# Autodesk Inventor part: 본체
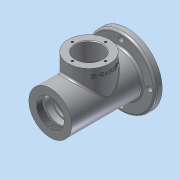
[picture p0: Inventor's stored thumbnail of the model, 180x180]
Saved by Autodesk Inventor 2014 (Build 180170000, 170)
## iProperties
Created: 2016-08
Part Number: 본체
Material: 알루미늄 6061
Document SubType Name: Modeling
Designer: 406-0014
Density: 2.71 g/cm^3
Appearance: 알루미늄 - 평지
Mass: 731.657 g
Surface Area: 616.228 cm^2
Volume: 269.984 cm^3
Author: 406-0014
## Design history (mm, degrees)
sketch "스케치1"
  geometry: C1 r 50 at (0, 0); 1 further point
  constraints: 1 centre point, 1 coincident
  dimensions: "d0" = 100 diameter of C1
extrude "돌출1" new body sketch "스케치1" distance "d1" = 10; taper "d2" = 0 deg
sketch "스케치2"
  geometry: C1 r 50 at (0, 0) reference; C2 r 31 at (0, 0)
  constraints: 1 centre point, 1 coincident
  dimensions: "d3" = 62 diameter of C2
extrude "돌출2" join sketch "스케치2" distance "d4" = 3; taper "d5" = 0 deg
sketch "스케치3"
  geometry: C1 r 50 at (0, 0) reference; C2 r 31 at (0, 0)
  constraints: 1 centre point, 1 coincident
  dimensions: "d6" = 62 diameter of C2
extrude "돌출3" join sketch "스케치3" distance "d7" = 102; taper "d8" = 0 deg
node "작업 평면1"
sketch "스케치4"
  geometry: L1 (-31, -102)-(31, -102) reference; C1 r 30 at (0, -46); 1 further point
  constraints: 1 centre point, 1 vertical alignment
  dimensions: "d10" = 60 diameter of C1; "d11" = 56 distance from line of L1 C1.centre
extrude "돌출4" join sketch "스케치4" stored distance "d12" = 102; taper "d13" = 0 deg
sketch "스케치5"
  geometry: C1 r 31 at (0, 0) reference; C2 r 50 at (0, 0) reference; 1 further point
  constraints: 1 coincident
hole "구멍1" sketch "스케치5" at (0, 0) diameter "d14" = 40.376; stored, may be unused: countersink angle "d18" = 90 deg, drill point angle "d20" = 0 deg; dims "d15" = 9, "d16" = 4, "d17" = 2, "d19" = 9
sketch "스케치6"
  geometry: L1 (0, -102.598)-(0, 13); L2 (-20.188, -93)-(20.188, -93) reference; L3 (0, -93)-(-24, -93); L4 (-24, -93)-(-24, -90); L5 (-24, -90)-(-20, -90); L6 (-20, -90)-(-20, -81); L7 (-20, -81)-(-17.5, -81); L8 (-17.5, -81)-(-17.5, -77.75); L9 (-17.5, -77.75)-(-18.5, -77.75); L10 (-18.5, -77.75)-(-18.5, -76); L11 (-18.5, -76)-(-17.5, -76); L12 (-17.5, -76)-(-17.5, -65); L13 (-17.5, -65)-(-26, -65); L14 (-26, -65)-(-26, -27); L15 (-26, -27)-(0, -27); L16 (20.188, -102)-(-20.188, -102) reference; L17 (-49, -16)-(-49, -76) reference; L18 (0, -93)-(0, -27); 3 further points
  constraints: 30 end point, 7 parallel, 7 perpendicular, 3 midpoint, 1 collinear, 1 horizontal alignment, 1 point on line, 1 vertical, 1 vertical alignment
  dimensions: "d23" = 3 distance between parallel lines of L5 L3; "d24" = 21 distance between parallel lines of L7 L16; "d25" = 1.75 distance between parallel lines of L9 L11; "d26" = 37 diameter of L10 L1; "d27" = 48 diameter of L4 L1; "d28" = 40 diameter of L6 L1; "d29" = 35 diameter of L8 L1; "d30" = 26 distance between parallel lines of L11 L16; "d31" = 35 diameter of L12 L1; "d32" = 52 diameter of L14 L1; "d45" = 38 distance between parallel lines of L15 L13; "d46" = 115.59757 distance of L1.start L1.end
revolve "회전1" sketch "스케치6" stored, may be unused: angle "d47" = 90 deg
sketch "스케치7"
  geometry: L1 (0, 15.236)-(0, -119.929); L2 (-26, -27)-(26, -27) reference; L3 (31, 13)-(-31, 13) reference; L4 (-17.5, -27)-(-17.5, -16.7); L5 (-17.5, -16.7)-(-16.5, -16.7); L6 (-16.5, -16.7)-(-16.5, -11.7); L7 (-16.5, -11.7)-(-10, -11.7); L8 (-10, -11.7)-(-10, -9); L9 (-12.904, -1)-(-16, -1); L10 (-16, -1)-(-21, 13); L11 (-10, -9)-(-12.5, -9); L12 (-12.5, -9)-(-12.5, -1.7); L13 (-12.5, -1.7)-(-12.904, -1); L14 (-17.5, -27)-(0, -27); L15 (-21, 13)-(0, 13); L16 (0, -27)-(0, 13); 1 further point
  constraints: 28 end point, 6 perpendicular, 3 parallel, 2 midpoint, 2 point on line, 1 vertical, 1 vertical alignment
  dimensions: "d48" = 42 diameter of L10.end L1; "d49" = 33 diameter of L6 L1; "d50" = 35 diameter of L4 L1; "d51" = 32 diameter of L9.end L1; "d52" = 30 deg angle of L12 L13; "d53" = 25 diameter of L12 L1; "d54" = 20 diameter of L8 L1; "d55" = 0.7 distance from line of L9 L12.end; "d56" = 14 distance between parallel lines of L3 L9; "d57" = 7.3 distance from line of L11 L12.end; "d58" = 2.7 distance between parallel lines of L11 L7; "d59" = 5 distance between parallel lines of L7 L5; "d60" = 135.16522 distance of L1.start L1.end
revolve "회전2" sketch "스케치7" stored, may be unused: angle "d61" = 90 deg
fillet "모깎기1" dims "d62" = 3
fillet "모깎기2" dims "d63" = 0.3
chamfer "모따기1" distance "d64" = 1; stored, may be unused: second distance "d65" = 2, angle "d66" = 45 deg
fillet "모깎기3" dims "d67" = 3
fillet "모깎기4" dims "d68" = 0.3
sketch "스케치8"
  geometry: C1 r 30 at (0, 0) reference; C2 r 19 at (0, 0); 1 further point
  constraints: 1 centre point, 1 coincident
  dimensions: "d69" = 38 diameter of C2
extrude "돌출5" cut sketch "스케치8" stored distance "d70" = 102; taper "d71" = 0 deg
chamfer "모따기2" distance "d72" = 1; stored, may be unused: second distance "d73" = 2, angle "d74" = 45 deg
sketch "스케치9" dims "d75" = 48
  geometry: C1 r 30 at (0, 0) reference; C2 r 20 at (0, 0) reference; 3 further points
  constraints: 2 vertical alignment, 1 coincident, 2 other
hole "구멍2" sketch "스케치9" at (0, 24) diameter "d76" = 3.242; stored, may be unused: countersink angle "d80" = 90 deg, drill point angle "d82" = 118 deg; dims "d77" = 8, "d78" = 4, "d79" = 2, "d81" = 10
sketch "스케치10" dims "d86" = 83
  geometry: C1 r 31 at (0, 0) reference; C2 r 50 at (0, 0) reference; C3 r 4 at (0, 41.5); 1 further point
  constraints: 2 vertical alignment, 1 centre point, 1 coincident, 2 other
  dimensions: "d87" = 8 diameter of C3
extrude "돌출6" cut sketch "스케치10" stored distance "d88" = 102; taper "d89" = 0 deg
fillet "모깎기5" dims "d93" = 3
fillet "모깎기6" dims "d94" = 3
fillet "모깎기7" dims "d95" = 3
node "작업 평면2"
sketch "스케치11"
  geometry: L1 (-31, -102)-(31, -102) reference; L2 (-49, -16)-(-49, -76) reference; 2 further points
  constraints: 1 other
  dimensions: "d97" = 56 distance from line of L1 point (-39, -46); "d98" = 10 distance from line of L2 point (-39, -46)
feature "엠보싱1" sketch "스케치11" dims "d2" = 0, "d99" = 0.5, "d100" = 0
fillet "모깎기8" dims "d101" = 3
node "솔리드1"
pattern_circular "원형 패턴1" dims angle "d84" = 360 deg
pattern_circular "원형 패턴2" dims angle "d91" = 360 deg
other parameters: "d9" = -49, "d96" = 48.5
